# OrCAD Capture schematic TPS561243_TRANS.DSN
size Custom
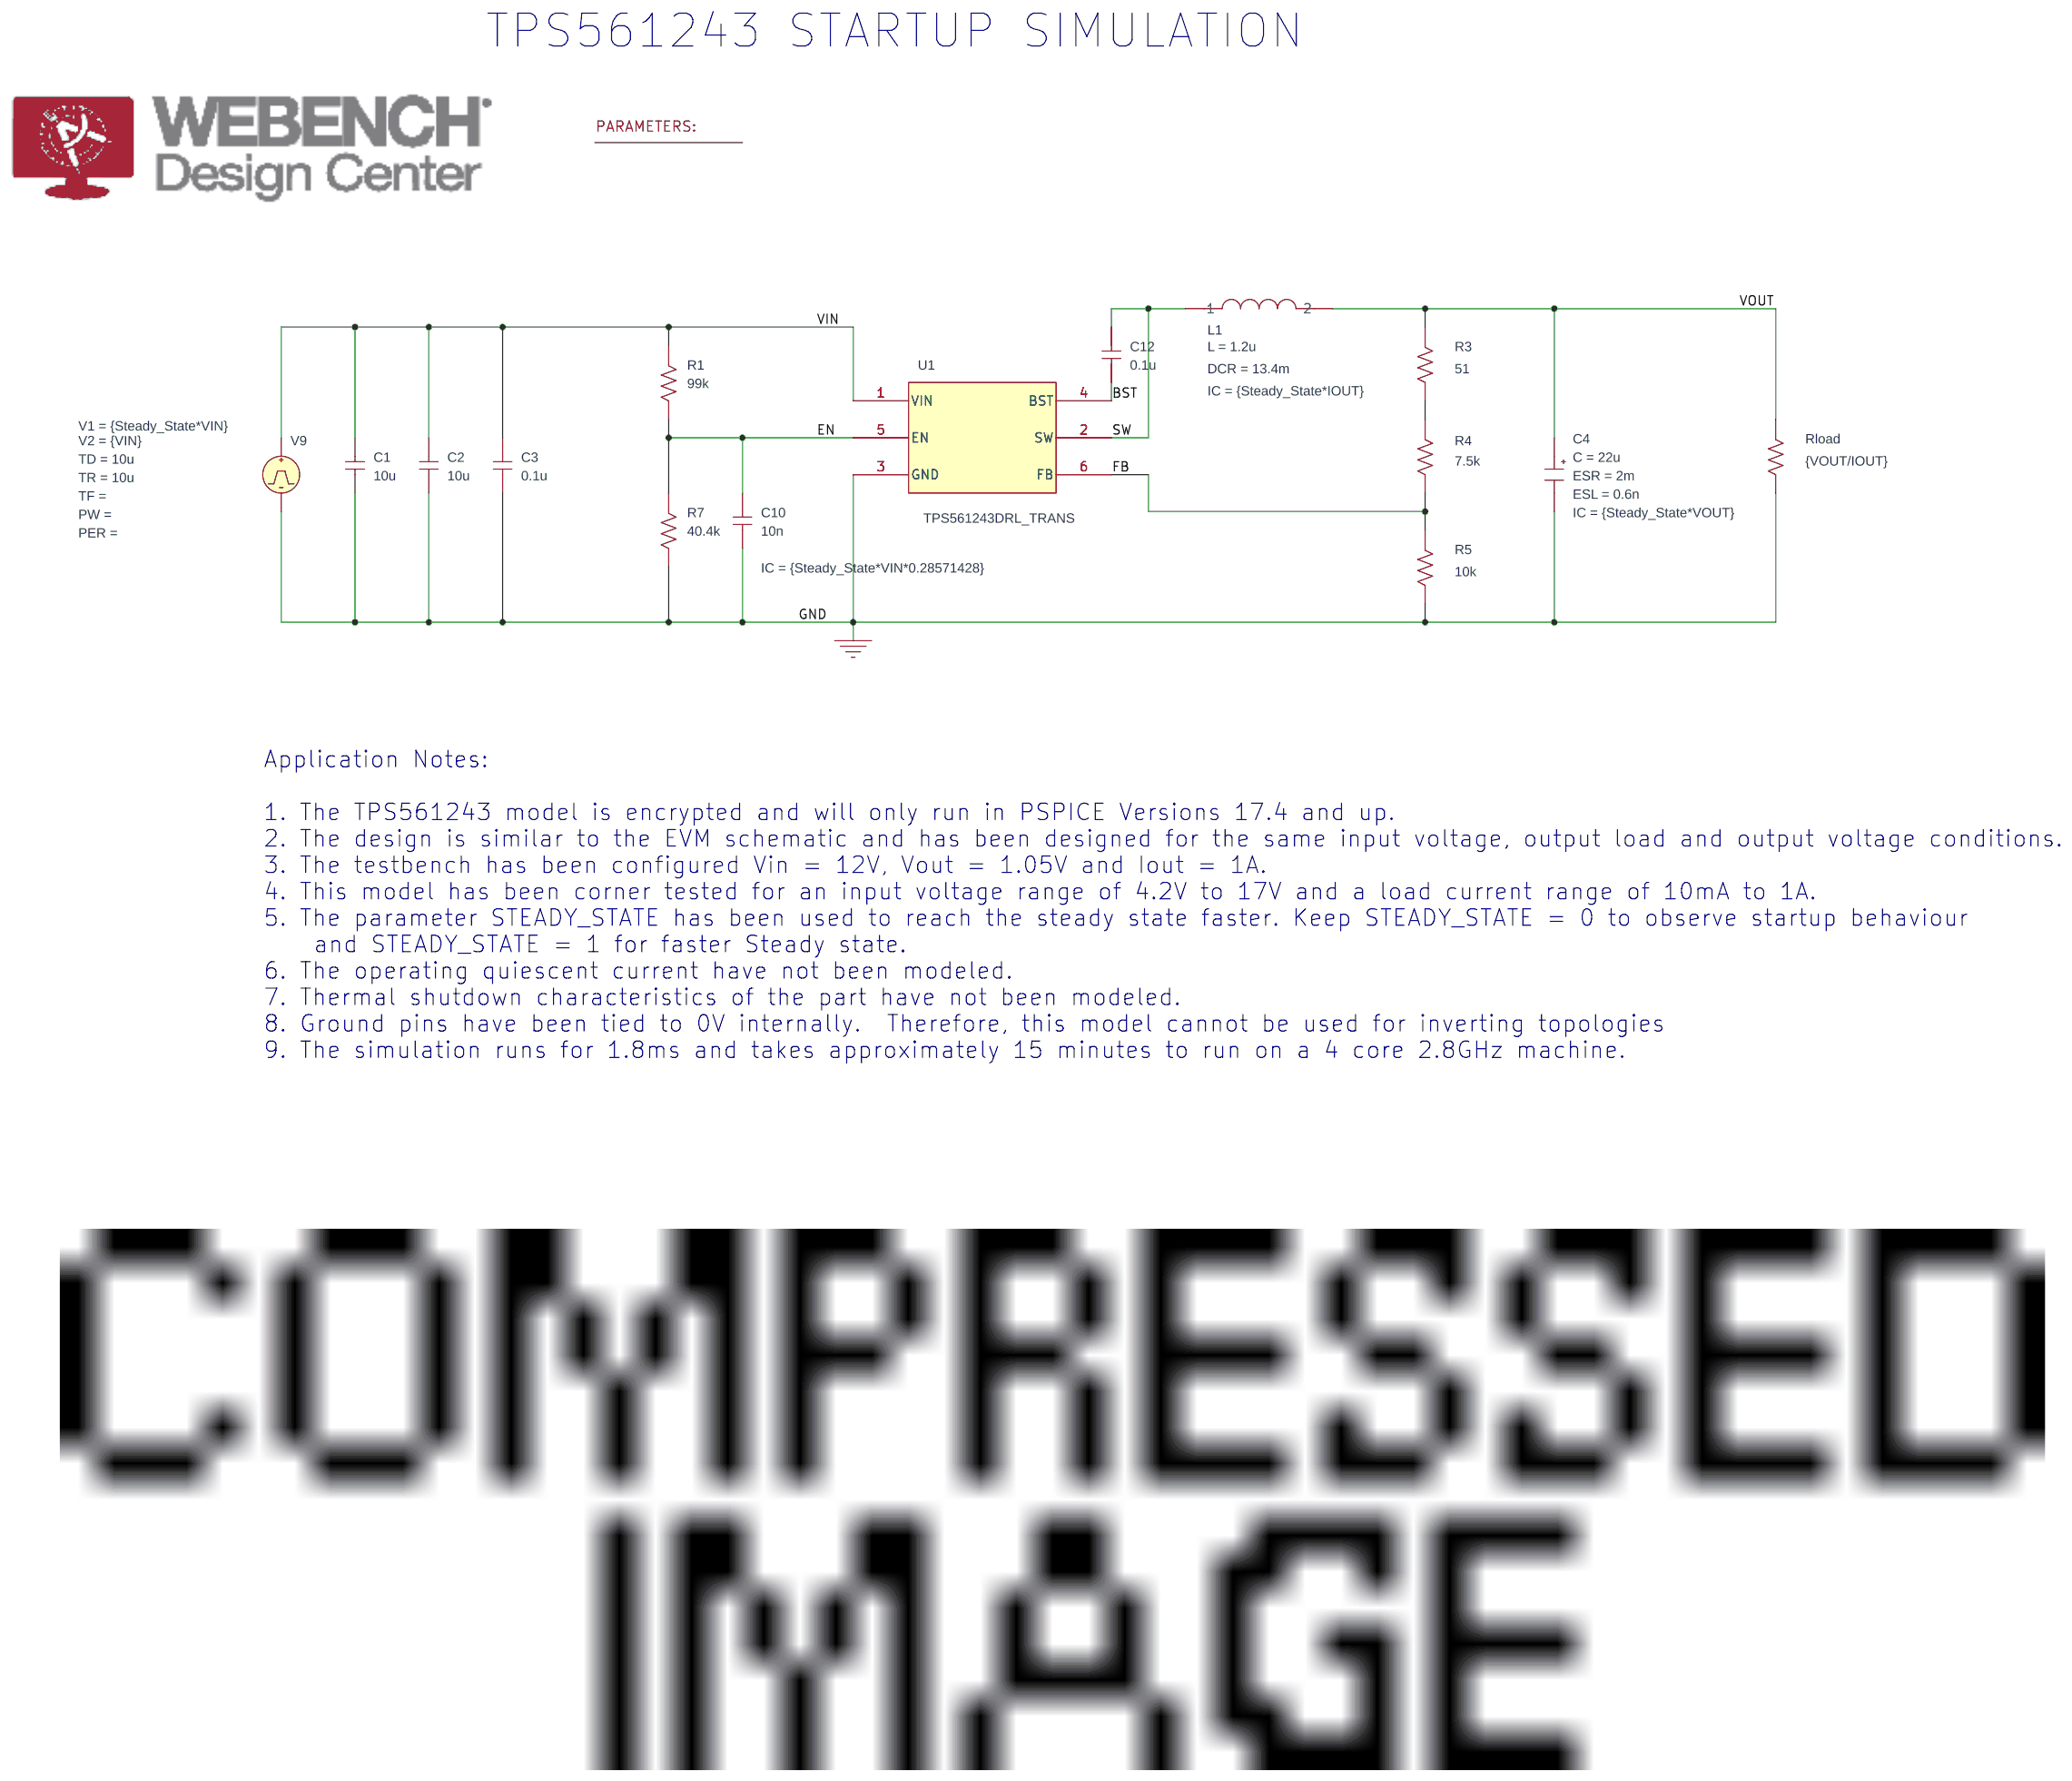
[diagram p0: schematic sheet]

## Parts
3  PARAM
C1  10u  [RAD/CK05]
C2  10u  [RAD/CK05]
C3  0.1u  [RAD/CK05]
C4  CESR
C10  10n  [RAD/CK05]
C12  0.1u  [RAD/CK05]
L1  LDCR
R1  99k  [AX/RC05]
R3  51  [AX/RC05]
R4  7.5k  [AX/RC05]
R5  10k  [AX/RC05]
R7  40.4k  [AX/RC05]
Rload  {VOUT/IOUT}  [AX/RC05]
U1  TPS561243DRL_TRANS
V9  VPULSE

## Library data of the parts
3 = PARAM: IOUT: 1; Steady_State: 0; VIN: 12; VOUT: 1.05
C1-C3 C12 = C
C4 = CESR_0: C: 22u; ESL: 0.6n; ESR: 2m; IC: {Steady_State*VOUT}
C10 = C: IC: {Steady_State*VIN*0.28571428}
L1 = LDCR: DCR: 13.4m; IC: {Steady_State*IOUT}; L: 1.2u
R1 R3-R5 R7 Rload = R
U1 = TPS561243_TRANS
V9 = VPULSE: TD: 10u; TR: 10u; V1: {Steady_State*VIN}; V2: {VIN}

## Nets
VIN: C1.1 C2.1 C3.1 R1.1 U1.1(VIN) V9.1(+)
0: C1.2 C2.2 C3.2 C4.2(OUT) C10.2 R5.2 R7.2 Rload.2 U1.3(GND) V9.2(-)
BST: C12.2 U1.4(BST)
EN: C10.1 R1.2 R7.1 U1.5(EN)
FB: R4.2 R5.1 U1.6(FB)
SW: C12.1 L1.1 U1.2(SW)
VOUT: C4.1(IN) L1.2 R3.1 Rload.1
N30034: R3.2 R4.1

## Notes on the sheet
- TPS561243 STARTUP SIMULATION
- Application Notes:
  1. The TPS561243 model is encrypted and will only run in PSPICE Versions 17.4 and up.
  2. The design is similar to the EVM schematic and has been designed for the same input voltage, output load and output voltage conditions.
  3. The testbench has been configured Vin = 12V, Vout = 1.05V and Iout = 1A.
  4. This model has been corner tested for an input voltage range of 4.2V to 17V and a load current range of 10mA to 1A.
  5. The parameter STEADY_STATE has been used to reach the steady state faster. Keep STEADY_STATE = 0 to observe startup behaviour
      and STEADY_STATE = 1 for faster Steady state.
  6. The operating quiescent current have not been modeled.
  7. Thermal shutdown characteristics of the part have not been modeled.
  8. Ground pins have been tied to 0V internally.  Therefore, this model cannot be used for inverting topologies
  9. The simulation runs for 1.8ms and takes approximately 15 minutes to run on a 4 core 2.8GHz machine.
